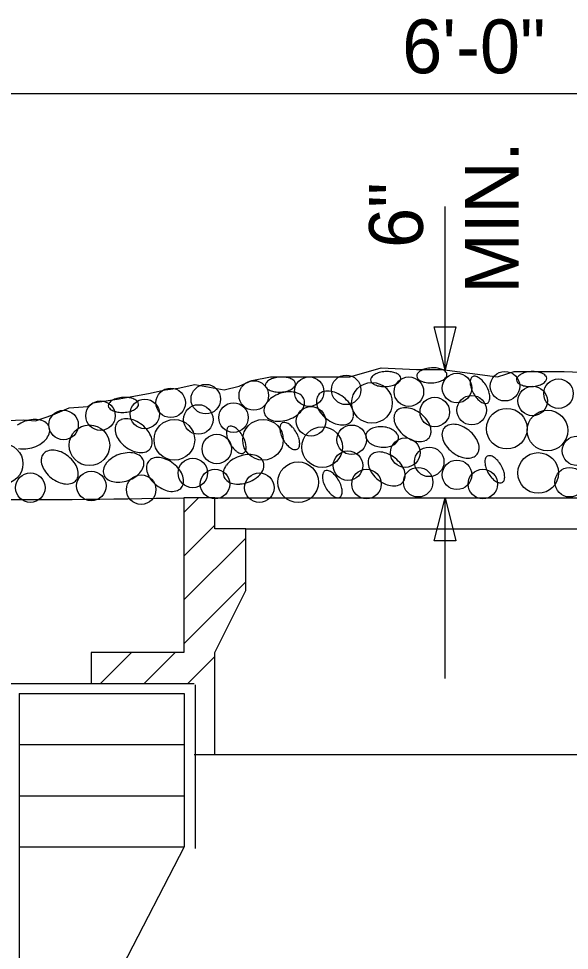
# Model space of a CAD drawing. Extents: x 9962.8 to 10024.8, y 9905.2 to 10002.8.
# Drawn here: x 9975.29 to 9985.97, y 9950.29 to 9968.36 of the extents above; entities that cross this region are included whole.
import ezdxf

# ---------------------------------------------------------------- set-up
doc = ezdxf.new("R2010")
doc.units = 0
for name, color, linetype in [('Default', 7, 'Continuous'), ('G-ANNO-TEXT', 7, 'Continuous'), ('G-DETL-LINE', 7, 'Continuous'), ('G-DETL-OTLN', 7, 'Continuous'), ('G-DETL-PATT', 7, 'Continuous')]:
    doc.layers.add(name, color=color, linetype=linetype)

# ---------------------------------------------------------------- blocks, each defined once
blk = doc.blocks.new('TERARR')
at = {"layer": 'Default'}
blk.add_lwpolyline([(-0.667, 0.167), (0, 0), (-0.667, -0.167)], close=True, dxfattribs=at)

msp = doc.modelspace()

# ---------------------------------------------------------------- linework, layer by layer
at = {"layer": 'G-ANNO-TEXT'}
for p, q in [((9969.822, 9966.908), (9997.938, 9966.908)), ((9983.561, 9961.546), (9983.561, 9964.716)), ((9983.561, 9955.565), (9983.561, 9959.069))]:
    msp.add_line(p, q, dxfattribs=at)
at = {"layer": 'G-DETL-LINE'}
for p, q in [((9978.696, 9954.093), (9979.097, 9954.093)), ((9979.097, 9954.093), (9988.697, 9954.093))]:
    msp.add_line(p, q, dxfattribs=at)
msp.add_lwpolyline([(9974.897, 9960.559), (9975.396, 9960.58), (9975.617, 9960.559), (9975.956, 9960.675), (9976.275, 9960.813), (9976.635, 9960.835), (9976.73, 9960.909), (9977.202, 9960.981), (9977.811, 9961.088), (9978.134, 9961.159), (9978.384, 9961.196), (9978.706, 9961.267), (9979.279, 9961.159), (9979.566, 9961.231), (9979.817, 9961.339), (9980.175, 9961.41), (9980.676, 9961.41), (9981.714, 9961.41), (9982.323, 9961.589), (9983.004, 9961.554), (9983.505, 9961.554), (9984.579, 9961.41), (9984.902, 9961.517), (9985.868, 9961.517), (9986.692, 9961.482)], dxfattribs=at)
msp.add_arc((9975.629, 10082.749), 123.713, 267.30979, 271.32823, dxfattribs=at)
at = {"layer": 'G-DETL-OTLN'}
for p, q in [((9978.497, 9959.069), (9978.497, 9956.069)), ((9979.097, 9959.069), (9978.497, 9959.069)), ((9979.097, 9959.069), (9988.697, 9959.069)), ((9979.097, 9958.469), (9979.097, 9959.069)), ((9979.697, 9958.469), (9979.097, 9958.469)), ((9979.697, 9958.469), (9988.097, 9958.469)), ((9979.697, 9957.269), (9979.697, 9958.469)), ((9979.097, 9956.069), (9979.697, 9957.269)), ((9978.497, 9956.069), (9976.697, 9956.069)), ((9976.697, 9956.069), (9976.697, 9955.469)), ((9979.097, 9954.093), (9979.097, 9956.069)), ((9975.113, 9955.469), (9978.696, 9955.469)), ((9978.716, 9955.441), (9978.716, 9952.272)), ((9975.305, 9955.277), (9975.305, 9933.794)), ((9975.305, 9955.277), (9978.504, 9955.277)), ((9978.504, 9955.277), (9978.504, 9952.301)), ((9978.504, 9952.301), (9977.304, 9949.986))]:
    msp.add_line(p, q, dxfattribs=at)
at = {"layer": 'G-DETL-PATT'}
for p, q in [((9978.497, 9958.785), (9978.781, 9959.069)), ((9978.497, 9957.936), (9979.097, 9958.536)), ((9978.497, 9957.088), (9979.697, 9958.288)), ((9978.497, 9956.239), (9979.697, 9957.439)), ((9976.878, 9955.469), (9977.478, 9956.069)), ((9977.726, 9955.469), (9978.326, 9956.069)), ((9978.574, 9955.469), (9979.097, 9955.991)), ((9975.305, 9954.285), (9978.504, 9954.285)), ((9975.305, 9953.293), (9978.504, 9953.293)), ((9975.305, 9952.301), (9978.504, 9952.301))]:
    msp.add_line(p, q, dxfattribs=at)
for centre, radius in [((9980.926, 9961.124), 0.286), ((9981.643, 9961.16), 0.286), ((9982.86, 9961.124), 0.286), ((9983.791, 9961.195), 0.286), ((9984.722, 9961.231), 0.286), ((9978.921, 9960.981), 0.286), ((9979.852, 9961.052), 0.286), ((9982.144, 9960.909), 0.394), ((9985.259, 9960.945), 0.286), ((9985.761, 9961.088), 0.286), ((9978.241, 9960.909), 0.286), ((9984.078, 9960.766), 0.286), ((9976.88, 9960.659), 0.286), ((9977.739, 9960.694), 0.286), ((9978.778, 9960.587), 0.286), ((9979.458, 9960.623), 0.286), ((9983.361, 9960.73), 0.286), ((9976.164, 9960.48), 0.286), ((9980.962, 9960.551), 0.286), ((9984.758, 9960.408), 0.394), ((9985.546, 9960.372), 0.394), ((9978.312, 9960.193), 0.394), ((9980.031, 9960.193), 0.394), ((9976.665, 9960.086), 0.394), ((9981.177, 9960.05), 0.394), ((9981.75, 9960.193), 0.286), ((9974.982, 9959.728), 0.394), ((9979.136, 9960.014), 0.286), ((9982.789, 9959.943), 0.286), ((9986.119, 9959.978), 0.286), ((9981.678, 9959.692), 0.286), ((9983.254, 9959.764), 0.286), ((9985.367, 9959.549), 0.394), ((9978.67, 9959.549), 0.286), ((9980.712, 9959.37), 0.394), ((9983.791, 9959.513), 0.286), ((9976.701, 9959.298), 0.286), ((9979.1, 9959.334), 0.286), ((9982.037, 9959.334), 0.286), ((9983.039, 9959.37), 0.286), ((9984.293, 9959.334), 0.286), ((9985.976, 9959.37), 0.286), ((9975.519, 9959.263), 0.286), ((9977.668, 9959.227), 0.286), ((9979.96, 9959.263), 0.286)]:
    msp.add_circle(centre, radius, dxfattribs=at)
for centre, radius, start, end in [((9983.273, 9961.212), 0.367, 104.6704, 119.3393), ((9983.33, 9960.991), 0.596, 93.1611, 104.6704), ((9983.33, 9960.991), 0.596, 81.6517, 93.1611), ((9983.363, 9961.217), 0.367, 66.9829, 81.6517), ((9980.336, 9961.033), 0.367, 104.6704, 119.3393), ((9980.394, 9960.812), 0.596, 93.1611, 104.6704), ((9980.394, 9960.812), 0.596, 81.6517, 93.1611), ((9980.427, 9961.038), 0.367, 66.9829, 81.6517), ((9982.192, 9961.358), 0.0756, 143.0435, 183.1611), ((9982.301, 9961.276), 0.211, 119.3393, 143.0435), ((9982.377, 9961.14), 0.367, 104.6704, 119.3393), ((9982.435, 9960.919), 0.596, 93.1611, 104.6704), ((9982.435, 9960.919), 0.596, 81.6517, 93.1611), ((9982.468, 9961.145), 0.367, 66.9829, 81.6517), ((9982.529, 9961.289), 0.211, 43.2786, 66.9829), ((9982.628, 9961.382), 0.0756, 3.1611, 43.2786), ((9982.628, 9961.382), 0.0756, 323.0435, 3.1611), ((9983.088, 9961.429), 0.0756, 143.0435, 183.1611), ((9983.088, 9961.429), 0.0756, 183.1611, 223.2786), ((9983.196, 9961.348), 0.211, 119.3393, 143.0435), ((9983.425, 9961.361), 0.211, 43.2786, 66.9829), ((9983.415, 9961.535), 0.211, 299.3393, 323.0435), ((9983.523, 9961.453), 0.0756, 3.1611, 43.2786), ((9983.523, 9961.453), 0.0756, 323.0435, 3.1611), ((9984.131, 9961.349), 0.0756, 119.7352, 159.8528), ((9984.131, 9961.349), 0.0756, 79.6177, 119.7352), ((9984.106, 9961.216), 0.211, 55.9134, 79.6177), ((9984.019, 9961.086), 0.367, 41.2446, 55.9134), ((9985.021, 9961.358), 0.0756, 143.0435, 183.1611), ((9985.13, 9961.276), 0.211, 119.3393, 143.0435), ((9985.206, 9961.14), 0.367, 104.6704, 119.3393), ((9985.264, 9960.919), 0.596, 93.1611, 104.6704), ((9985.264, 9960.919), 0.596, 81.6517, 93.1611), ((9985.297, 9961.145), 0.367, 66.9829, 81.6517), ((9985.358, 9961.289), 0.211, 43.2786, 66.9829), ((9985.457, 9961.382), 0.0756, 3.1611, 43.2786), ((9985.457, 9961.382), 0.0756, 323.0435, 3.1611), ((9980.151, 9961.25), 0.0756, 143.0435, 183.1611), ((9980.151, 9961.25), 0.0756, 183.1611, 223.2786), ((9980.259, 9961.169), 0.211, 119.3393, 143.0435), ((9980.488, 9961.182), 0.211, 43.2786, 66.9829), ((9980.479, 9961.356), 0.211, 299.3393, 323.0435), ((9980.587, 9961.274), 0.0756, 3.1611, 43.2786), ((9980.587, 9961.274), 0.0756, 323.0435, 3.1611), ((9982.192, 9961.358), 0.0756, 183.1611, 223.2786), ((9982.291, 9961.45), 0.211, 223.2786, 246.9829), ((9982.352, 9961.595), 0.367, 246.9829, 261.6517), ((9982.385, 9961.82), 0.596, 261.6517, 273.1611), ((9982.385, 9961.82), 0.596, 273.1611, 284.6704), ((9982.443, 9961.6), 0.367, 284.6704, 299.3393), ((9982.52, 9961.463), 0.211, 299.3393, 323.0435), ((9983.186, 9961.522), 0.211, 223.2786, 246.9829), ((9983.247, 9961.666), 0.367, 246.9829, 261.6517), ((9983.281, 9961.892), 0.596, 261.6517, 273.1611), ((9983.281, 9961.892), 0.596, 273.1611, 284.6704), ((9983.338, 9961.671), 0.367, 284.6704, 299.3393), ((9984.258, 9961.302), 0.211, 159.8528, 183.557), ((9984.414, 9961.312), 0.367, 183.557, 198.2258), ((9983.847, 9960.936), 0.596, 29.7352, 41.2446), ((9983.847, 9960.936), 0.596, 18.2258, 29.7352), ((9985.021, 9961.358), 0.0756, 183.1611, 223.2786), ((9985.12, 9961.45), 0.211, 223.2786, 246.9829), ((9985.181, 9961.595), 0.367, 246.9829, 261.6517), ((9985.214, 9961.82), 0.596, 261.6517, 273.1611), ((9985.214, 9961.82), 0.596, 273.1611, 284.6704), ((9985.272, 9961.6), 0.367, 284.6704, 299.3393), ((9985.349, 9961.463), 0.211, 299.3393, 323.0435), ((9980.25, 9961.343), 0.211, 223.2786, 246.9829), ((9980.311, 9961.487), 0.367, 246.9829, 261.6517), ((9980.564, 9960.499), 0.625, 109.6611, 124.758), ((9980.344, 9961.713), 0.596, 261.6517, 273.1611), ((9980.564, 9960.499), 0.625, 94.5642, 109.6611), ((9980.344, 9961.713), 0.596, 273.1611, 284.6704), ((9980.402, 9961.492), 0.367, 284.6704, 299.3393), ((9980.549, 9960.682), 0.442, 76.5864, 94.5642), ((9980.58, 9960.812), 0.309, 52.1181, 76.5864), ((9980.661, 9960.915), 0.177, 19.6611, 52.1181), ((9981.245, 9960.952), 0.177, 141.6767, 174.1337), ((9981.245, 9960.952), 0.177, 109.2198, 141.6767), ((9981.288, 9960.828), 0.309, 84.7515, 109.2198), ((9981.275, 9960.696), 0.442, 66.7736, 84.7515), ((9981.203, 9960.527), 0.625, 51.6767, 66.7736), ((9984.631, 9961.384), 0.596, 198.2258, 209.7352), ((9984.631, 9961.384), 0.596, 209.7352, 221.2446), ((9984.064, 9961.007), 0.367, 3.557, 18.2258), ((9984.22, 9961.017), 0.211, 339.8528, 3.557), ((9977.107, 9960.857), 0.0756, 143.0435, 183.1611), ((9977.107, 9960.857), 0.0756, 183.1611, 223.2786), ((9977.216, 9960.775), 0.211, 119.3393, 143.0435), ((9977.292, 9960.639), 0.367, 104.6704, 119.3393), ((9977.35, 9960.418), 0.596, 93.1611, 104.6704), ((9977.35, 9960.418), 0.596, 81.6517, 93.1611), ((9977.383, 9960.644), 0.367, 66.9829, 81.6517), ((9977.444, 9960.788), 0.211, 43.2786, 66.9829), ((9977.543, 9960.881), 0.0756, 3.1611, 43.2786), ((9977.543, 9960.881), 0.0756, 323.0435, 3.1611), ((9980.353, 9960.731), 0.309, 142.7358, 167.2041), ((9980.459, 9960.65), 0.442, 124.758, 142.7358), ((9980.533, 9960.944), 0.309, 322.7358, 347.2041), ((9980.661, 9960.915), 0.177, 347.2041, 19.6611), ((9981.375, 9960.939), 0.309, 174.1337, 198.602), ((9981.203, 9960.527), 0.625, 36.5799, 51.6767), ((9981.35, 9960.636), 0.442, 18.602, 36.5799), ((9984.459, 9961.233), 0.367, 221.2446, 235.9134), ((9984.371, 9961.103), 0.211, 235.9134, 259.6177), ((9984.347, 9960.97), 0.0756, 259.6177, 299.7352), ((9984.347, 9960.97), 0.0756, 299.7352, 339.8528), ((9977.206, 9960.949), 0.211, 223.2786, 246.9829), ((9977.267, 9961.093), 0.367, 246.9829, 261.6517), ((9977.3, 9961.319), 0.596, 261.6517, 273.1611), ((9977.3, 9961.319), 0.596, 273.1611, 284.6704), ((9977.358, 9961.098), 0.367, 284.6704, 299.3393), ((9977.435, 9960.962), 0.211, 299.3393, 323.0435), ((9980.225, 9960.76), 0.177, 167.2041, 199.6611), ((9980.225, 9960.76), 0.177, 199.6611, 232.1181), ((9980.427, 9961.025), 0.442, 304.758, 322.7358), ((9981.501, 9960.981), 0.442, 198.602, 216.5799), ((9981.649, 9961.091), 0.625, 216.5798, 231.6767), ((9981.477, 9960.679), 0.309, 354.1337, 18.602), ((9982.749, 9960.63), 0.177, 141.6767, 174.1337), ((9982.749, 9960.63), 0.177, 109.2198, 141.6767), ((9982.792, 9960.506), 0.309, 84.7515, 109.2198), ((9982.779, 9960.373), 0.442, 66.7736, 84.7515), ((9982.707, 9960.205), 0.625, 51.6767, 66.7736), ((9982.707, 9960.205), 0.625, 36.5799, 51.6767), ((9975.622, 9959.962), 0.625, 109.6611, 124.758), ((9975.622, 9959.962), 0.625, 94.5642, 109.6611), ((9975.607, 9960.145), 0.442, 76.5864, 94.5642), ((9975.638, 9960.275), 0.309, 52.1181, 76.5864), ((9975.719, 9960.378), 0.177, 19.6611, 52.1181), ((9977.341, 9960.415), 0.177, 141.6767, 174.1337), ((9977.341, 9960.415), 0.177, 109.2198, 141.6767), ((9977.384, 9960.291), 0.309, 84.7515, 109.2198), ((9977.372, 9960.159), 0.442, 66.7736, 84.7515), ((9977.3, 9959.99), 0.625, 51.6767, 66.7736), ((9980.306, 9960.863), 0.309, 232.1181, 256.5864), ((9980.337, 9960.993), 0.442, 256.5864, 274.5642), ((9980.442, 9960.454), 0.0756, 119.7352, 159.8528), ((9980.322, 9961.176), 0.625, 274.5642, 289.6611), ((9980.442, 9960.454), 0.0756, 79.6177, 119.7352), ((9980.418, 9960.321), 0.211, 55.9134, 79.6177), ((9980.322, 9961.176), 0.625, 289.6611, 304.758), ((9980.33, 9960.191), 0.367, 41.2446, 55.9134), ((9981.649, 9961.091), 0.625, 231.6767, 246.7736), ((9981.576, 9960.922), 0.442, 246.7736, 264.7515), ((9981.564, 9960.789), 0.309, 264.7515, 289.2198), ((9981.607, 9960.665), 0.177, 289.2198, 321.6767), ((9981.607, 9960.665), 0.177, 321.6767, 354.1337), ((9982.879, 9960.617), 0.309, 174.1337, 198.602), ((9983.005, 9960.659), 0.442, 198.602, 216.5799), ((9982.854, 9960.314), 0.442, 18.602, 36.5799), ((9983.723, 9960.184), 0.309, 84.7515, 109.2198), ((9983.711, 9960.051), 0.442, 66.7736, 84.7515), ((9975.591, 9960.407), 0.309, 322.7358, 347.2041), ((9975.719, 9960.378), 0.177, 347.2041, 19.6611), ((9977.472, 9960.402), 0.309, 174.1337, 198.602), ((9977.598, 9960.444), 0.442, 198.602, 216.5799), ((9977.3, 9959.99), 0.625, 36.5799, 51.6767), ((9977.447, 9960.099), 0.442, 18.602, 36.5799), ((9979.531, 9960.336), 0.211, 159.8528, 183.557), ((9979.687, 9960.346), 0.367, 183.557, 198.2258), ((9979.404, 9960.383), 0.0756, 119.7352, 159.8528), ((9979.404, 9960.383), 0.0756, 79.6177, 119.7352), ((9979.379, 9960.25), 0.211, 55.9134, 79.6177), ((9979.292, 9960.12), 0.367, 41.2446, 55.9134), ((9979.12, 9959.969), 0.596, 29.7352, 41.2446), ((9980.569, 9960.408), 0.211, 159.8528, 183.557), ((9980.726, 9960.417), 0.367, 183.557, 198.2258), ((9980.942, 9960.489), 0.596, 198.2258, 209.7352), ((9980.159, 9960.041), 0.596, 29.7352, 41.2446), ((9980.159, 9960.041), 0.596, 18.2258, 29.7352), ((9982.151, 9960.264), 0.127, 141.1979, 174.8035), ((9982.236, 9960.196), 0.236, 116.7392, 141.1979), ((9982.287, 9960.094), 0.349, 99.2802, 116.7392), ((9982.313, 9959.939), 0.507, 84.8036, 99.2802), ((9982.313, 9959.939), 0.507, 70.3269, 84.8036), ((9982.366, 9960.087), 0.349, 52.8679, 70.3269), ((9982.434, 9960.178), 0.236, 28.4092, 52.8679), ((9983.153, 9960.768), 0.625, 216.5798, 231.6767), ((9983.111, 9960.343), 0.177, 321.6767, 354.1337), ((9982.981, 9960.357), 0.309, 354.1337, 18.602), ((9983.81, 9960.294), 0.309, 174.1337, 198.602), ((9983.68, 9960.308), 0.177, 141.6767, 174.1337), ((9983.68, 9960.308), 0.177, 109.2198, 141.6767), ((9983.638, 9959.883), 0.625, 51.6767, 66.7736), ((9983.638, 9959.883), 0.625, 36.5799, 51.6767), ((9975.38, 9960.639), 0.625, 289.6611, 304.758), ((9975.485, 9960.488), 0.442, 304.758, 322.7358), ((9977.745, 9960.554), 0.625, 216.5798, 231.6767), ((9977.574, 9960.142), 0.309, 354.1337, 18.602), ((9979.904, 9960.417), 0.596, 198.2258, 209.7352), ((9979.904, 9960.417), 0.596, 209.7352, 221.2446), ((9979.12, 9959.969), 0.596, 18.2258, 29.7352), ((9979.337, 9960.041), 0.367, 3.557, 18.2258), ((9980.942, 9960.489), 0.596, 209.7352, 221.2446), ((9980.375, 9960.112), 0.367, 3.557, 18.2258), ((9980.532, 9960.122), 0.211, 339.8528, 3.557), ((9982.151, 9960.264), 0.127, 174.8036, 208.4092), ((9982.247, 9960.316), 0.236, 208.4092, 232.8679), ((9982.316, 9960.407), 0.349, 232.8679, 250.3269), ((9982.445, 9960.298), 0.236, 296.7392, 321.1979), ((9982.531, 9960.23), 0.127, 321.1979, 354.8035), ((9982.531, 9960.23), 0.127, 354.8036, 28.4092), ((9983.153, 9960.768), 0.625, 231.6767, 246.7736), ((9983.08, 9960.6), 0.442, 246.7736, 264.7515), ((9983.068, 9960.467), 0.309, 264.7515, 289.2198), ((9983.111, 9960.343), 0.177, 289.2198, 321.6767), ((9983.936, 9960.337), 0.442, 198.602, 216.5799), ((9983.785, 9959.992), 0.442, 18.602, 36.5799), ((9983.912, 9960.035), 0.309, 354.1337, 18.602), ((9975.395, 9960.456), 0.442, 256.5864, 274.5642), ((9975.38, 9960.639), 0.625, 274.5642, 289.6611), ((9975.909, 9959.807), 0.177, 109.2198, 141.6767), ((9975.952, 9959.683), 0.309, 84.7515, 109.2198), ((9975.94, 9959.55), 0.442, 66.7736, 84.7515), ((9975.868, 9959.382), 0.625, 51.6767, 66.7736), ((9977.448, 9959.318), 0.625, 94.5642, 109.6611), ((9977.745, 9960.554), 0.625, 231.6767, 246.7736), ((9977.434, 9959.501), 0.442, 76.5864, 94.5642), ((9977.673, 9960.385), 0.442, 246.7736, 264.7515), ((9977.661, 9960.252), 0.309, 264.7515, 289.2198), ((9977.704, 9960.129), 0.177, 289.2198, 321.6767), ((9977.704, 9960.129), 0.177, 321.6767, 354.1337), ((9979.732, 9960.267), 0.367, 221.2446, 235.9134), ((9979.644, 9960.137), 0.211, 235.9134, 259.6177), ((9979.62, 9960.004), 0.0756, 299.7352, 339.8528), ((9979.493, 9960.05), 0.211, 339.8528, 3.557), ((9980.771, 9960.338), 0.367, 221.2446, 235.9134), ((9980.683, 9960.209), 0.211, 235.9134, 259.6177), ((9980.659, 9960.076), 0.0756, 259.6177, 299.7352), ((9980.659, 9960.076), 0.0756, 299.7352, 339.8528), ((9982.29, 9959.647), 0.309, 84.7515, 109.2198), ((9982.369, 9960.555), 0.507, 250.3269, 264.8036), ((9982.278, 9959.514), 0.442, 66.7736, 84.7515), ((9982.369, 9960.555), 0.507, 264.8036, 279.2802), ((9982.394, 9960.4), 0.349, 279.2802, 296.7392), ((9984.084, 9960.446), 0.625, 216.5798, 231.6767), ((9984.084, 9960.446), 0.625, 231.6767, 246.7736), ((9984.042, 9960.021), 0.177, 321.6767, 354.1337), ((9976.039, 9959.793), 0.309, 174.1337, 198.602), ((9975.909, 9959.807), 0.177, 141.6767, 174.1337), ((9975.868, 9959.382), 0.625, 36.5799, 51.6767), ((9977.344, 9959.469), 0.442, 124.758, 142.7358), ((9977.448, 9959.318), 0.625, 109.6611, 124.758), ((9977.465, 9959.631), 0.309, 52.1181, 76.5864), ((9977.545, 9959.734), 0.177, 19.6611, 52.1181), ((9977.545, 9959.734), 0.177, 347.2041, 19.6611), ((9977.95, 9959.664), 0.177, 141.6767, 174.1337), ((9977.95, 9959.664), 0.177, 109.2198, 141.6767), ((9977.993, 9959.54), 0.309, 84.7515, 109.2198), ((9977.981, 9959.407), 0.442, 66.7736, 84.7515), ((9977.909, 9959.238), 0.625, 51.6767, 66.7736), ((9979.672, 9959.433), 0.442, 124.758, 142.7358), ((9979.776, 9959.282), 0.625, 109.6611, 124.758), ((9979.776, 9959.282), 0.625, 94.5642, 109.6611), ((9979.62, 9960.004), 0.0756, 259.6177, 299.7352), ((9979.761, 9959.465), 0.442, 76.5864, 94.5642), ((9979.792, 9959.595), 0.309, 52.1181, 76.5864), ((9979.873, 9959.698), 0.177, 19.6611, 52.1181), ((9982.378, 9959.758), 0.309, 174.1337, 198.602), ((9982.247, 9959.771), 0.177, 141.6767, 174.1337), ((9982.247, 9959.771), 0.177, 109.2198, 141.6767), ((9982.206, 9959.346), 0.625, 51.6767, 66.7736), ((9982.206, 9959.346), 0.625, 36.5799, 51.6767), ((9984.011, 9960.278), 0.442, 246.7736, 264.7515), ((9983.999, 9960.145), 0.309, 264.7515, 289.2198), ((9984.042, 9960.021), 0.177, 289.2198, 321.6767), ((9984.544, 9959.763), 0.211, 159.8528, 183.557), ((9984.417, 9959.81), 0.0756, 119.7352, 159.8528), ((9984.417, 9959.81), 0.0756, 79.6177, 119.7352), ((9984.393, 9959.677), 0.211, 55.9134, 79.6177), ((9984.305, 9959.547), 0.367, 41.2446, 55.9134), ((9984.133, 9959.397), 0.596, 29.7352, 41.2446), ((9976.166, 9959.836), 0.442, 198.602, 216.5799), ((9976.015, 9959.491), 0.442, 18.602, 36.5799), ((9976.141, 9959.533), 0.309, 354.1337, 18.602), ((9977.11, 9959.579), 0.177, 167.2041, 199.6611), ((9977.238, 9959.549), 0.309, 142.7358, 167.2041), ((9977.417, 9959.763), 0.309, 322.7358, 347.2041), ((9978.08, 9959.65), 0.309, 174.1337, 198.602), ((9977.909, 9959.238), 0.625, 36.5799, 51.6767), ((9978.056, 9959.348), 0.442, 18.602, 36.5799), ((9979.437, 9959.543), 0.177, 167.2041, 199.6611), ((9979.565, 9959.514), 0.309, 142.7358, 167.2041), ((9979.745, 9959.727), 0.309, 322.7358, 347.2041), ((9979.873, 9959.698), 0.177, 347.2041, 19.6611), ((9981.266, 9959.523), 0.0756, 119.7352, 159.8528), ((9981.266, 9959.523), 0.0756, 79.6177, 119.7352), ((9981.242, 9959.39), 0.211, 55.9134, 79.6177), ((9982.504, 9959.8), 0.442, 198.602, 216.5799), ((9982.353, 9959.455), 0.442, 18.602, 36.5799), ((9982.479, 9959.498), 0.309, 354.1337, 18.602), ((9984.7, 9959.773), 0.367, 183.557, 198.2258), ((9984.917, 9959.844), 0.596, 198.2258, 209.7352), ((9984.133, 9959.397), 0.596, 18.2258, 29.7352), ((9984.35, 9959.468), 0.367, 3.557, 18.2258), ((9976.313, 9959.945), 0.625, 216.5798, 231.6767), ((9976.313, 9959.945), 0.625, 231.6767, 246.7736), ((9976.272, 9959.52), 0.177, 289.2198, 321.6767), ((9976.272, 9959.52), 0.177, 321.6767, 354.1337), ((9977.11, 9959.579), 0.177, 199.6611, 232.1181), ((9977.19, 9959.682), 0.309, 232.1181, 256.5864), ((9977.207, 9959.994), 0.625, 274.5642, 289.6611), ((9977.207, 9959.994), 0.625, 289.6611, 304.758), ((9977.311, 9959.844), 0.442, 304.758, 322.7358), ((9978.207, 9959.693), 0.442, 198.602, 216.5799), ((9978.354, 9959.802), 0.625, 216.5798, 231.6767), ((9978.182, 9959.39), 0.309, 354.1337, 18.602), ((9979.437, 9959.543), 0.177, 199.6611, 232.1181), ((9979.518, 9959.646), 0.309, 232.1181, 256.5864), ((9979.534, 9959.959), 0.625, 289.6611, 304.758), ((9979.639, 9959.808), 0.442, 304.758, 322.7358), ((9981.393, 9959.477), 0.211, 159.8528, 183.557), ((9981.549, 9959.487), 0.367, 183.557, 198.2258), ((9981.154, 9959.261), 0.367, 41.2446, 55.9134), ((9980.982, 9959.11), 0.596, 29.7352, 41.2446), ((9980.982, 9959.11), 0.596, 18.2258, 29.7352), ((9982.651, 9959.909), 0.625, 216.5798, 231.6767), ((9982.651, 9959.909), 0.625, 231.6767, 246.7736), ((9982.61, 9959.484), 0.177, 321.6767, 354.1337), ((9984.917, 9959.844), 0.596, 209.7352, 221.2446), ((9984.746, 9959.694), 0.367, 221.2446, 235.9134), ((9984.633, 9959.431), 0.0756, 299.7352, 339.8528), ((9984.506, 9959.478), 0.211, 339.8528, 3.557), ((9976.241, 9959.777), 0.442, 246.7736, 264.7515), ((9976.228, 9959.644), 0.309, 264.7515, 289.2198), ((9977.221, 9959.812), 0.442, 256.5864, 274.5642), ((9978.354, 9959.802), 0.625, 231.6767, 246.7736), ((9978.282, 9959.633), 0.442, 246.7736, 264.7515), ((9978.313, 9959.377), 0.177, 289.2198, 321.6767), ((9978.313, 9959.377), 0.177, 321.6767, 354.1337), ((9979.549, 9959.776), 0.442, 256.5864, 274.5642), ((9979.534, 9959.959), 0.625, 274.5642, 289.6611), ((9981.766, 9959.558), 0.596, 198.2258, 209.7352), ((9981.766, 9959.558), 0.596, 209.7352, 221.2446), ((9981.199, 9959.182), 0.367, 3.557, 18.2258), ((9982.579, 9959.741), 0.442, 246.7736, 264.7515), ((9982.567, 9959.608), 0.309, 264.7515, 289.2198), ((9982.61, 9959.484), 0.177, 289.2198, 321.6767), ((9984.658, 9959.564), 0.211, 235.9134, 259.6177), ((9984.633, 9959.431), 0.0756, 259.6177, 299.7352), ((9978.27, 9959.501), 0.309, 264.7515, 289.2198), ((9981.594, 9959.408), 0.367, 221.2446, 235.9134), ((9981.507, 9959.278), 0.211, 235.9134, 259.6177), ((9981.482, 9959.145), 0.0756, 259.6177, 299.7352), ((9981.482, 9959.145), 0.0756, 299.7352, 339.8528), ((9981.355, 9959.191), 0.211, 339.8528, 3.557)]:
    msp.add_arc(centre, radius, start, end, dxfattribs=at)

# ---------------------------------------------------------------- block references
at = {"layer": 'G-ANNO-TEXT', "xscale": 1.24992, "yscale": 1.24992}
for p, rotation in [((9983.561, 9961.546), -90), ((9983.561, 9959.069), 90)]:
    msp.add_blockref('TERARR', p, dxfattribs=dict(at, rotation=rotation))

# ---------------------------------------------------------------- texts
at = {"layer": 'G-ANNO-TEXT'}
msp.add_text('6\'-0"', height=1.044, dxfattribs=at).set_placement((9982.73, 9967.297))
for s, p in [('MIN.', (9984.99, 9963.03)), ('6"', (9983.131, 9963.912))]:
    msp.add_text(s, height=1.044, rotation=90, dxfattribs=at).set_placement(p)

doc.saveas('drawing.dxf')
